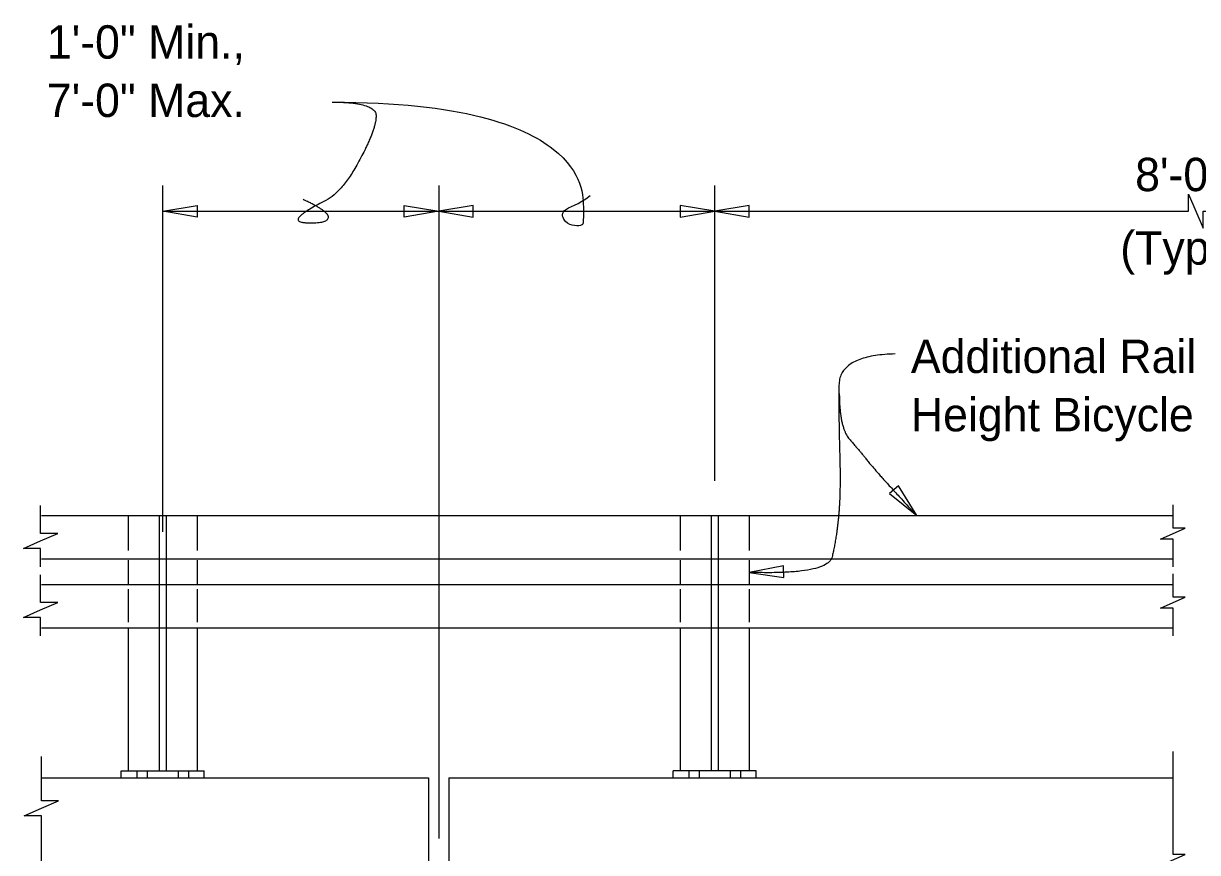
# Model space of a CAD drawing. Extents: x 120680.2 to 120752.3, y 120667.6 to 120707.3.
# Drawn here: x 120682.23 to 120689.32, y 120699.34 to 120704.35 of the extents above; entities that cross this region are included whole.
import ezdxf

# ---------------------------------------------------------------- set-up
doc = ezdxf.new("R2010")
doc.units = 0
for name, color, linetype in [('CL_Minor', 7, 'Continuous'), ('Dimension', 7, 'Continuous'), ('ParapetConc', 7, 'Continuous'), ('PedRail', 7, 'Continuous'), ('TextStructures', 7, 'Continuous')]:
    doc.layers.add(name, color=color, linetype=linetype)

msp = doc.modelspace()

# ---------------------------------------------------------------- linework, layer by layer
at = {"layer": 'CL_Minor'}
msp.add_line((120684.7404, 120703.3696), (120684.7404, 120699.4277), dxfattribs=at)
at = {"layer": 'Dimension'}
for p, q in [((120683.0736, 120701.279), (120683.0736, 120703.3696)), ((120686.4071, 120701.5877), (120686.4071, 120703.3696))]:
    msp.add_line(p, q, dxfattribs=at)
for points in [[(120686.4071, 120703.2151), (120689.2675, 120703.2151), (120689.2675, 120703.3184), (120689.3125, 120703.2151), (120689.3575, 120703.1117), (120689.3575, 120703.2151), (120693.5939, 120703.2151)], [(120683.0736, 120703.2151), (120684.7404, 120703.2151)], [(120684.7404, 120703.2151), (120686.4071, 120703.2151)], [(120682.3361, 120701.0691), (120682.3361, 120701.1797), (120682.2328, 120701.1797), (120682.3361, 120701.2247), (120682.4394, 120701.2697), (120682.3361, 120701.2697), (120682.3361, 120701.4377)], [(120689.1759, 120701.069), (120689.1759, 120701.2356), (120689.0984, 120701.2356), (120689.2484, 120701.3018), (120689.1759, 120701.3018), (120689.1759, 120701.4427)], [(120682.3361, 120700.6524), (120682.3361, 120700.7631), (120682.2328, 120700.7631), (120682.3361, 120700.8081), (120682.4394, 120700.8531), (120682.3361, 120700.8531), (120682.3361, 120701.021)], [(120689.1759, 120700.6523), (120689.1759, 120700.8189), (120689.0984, 120700.8189), (120689.2484, 120700.8852), (120689.1759, 120700.8852), (120689.1759, 120701.026)], [(120689.1748, 120698.3779), (120689.1748, 120699.2651), (120689.0973, 120699.2651), (120689.2473, 120699.3314), (120689.1748, 120699.3314), (120689.1748, 120699.9541)], [(120682.341, 120698.7651), (120682.341, 120699.566), (120682.2376, 120699.566), (120682.341, 120699.611), (120682.4443, 120699.656), (120682.341, 120699.656), (120682.341, 120699.9246)]]:
    msp.add_lwpolyline(points, dxfattribs=at)
for points in [[(120683.0736, 120703.2151), (120683.2819, 120703.2503), (120683.2819, 120703.1798)], [(120684.7404, 120703.2151), (120684.5321, 120703.1798), (120684.5321, 120703.2503)], [(120684.7404, 120703.2151), (120684.9486, 120703.1798), (120684.9486, 120703.2503)], [(120686.4071, 120703.2151), (120686.1988, 120703.2503), (120686.1988, 120703.1798)], [(120686.4071, 120703.2151), (120686.6153, 120703.1798), (120686.6153, 120703.2503)], [(120687.6271, 120701.3779), (120687.5162, 120701.5577), (120687.4632, 120701.5111)], [(120686.6154, 120701.0348), (120686.8243, 120701.0036), (120686.8229, 120701.0742)]]:
    msp.add_lwpolyline(points, close=True, dxfattribs=at)
for points, degree in [([(120684.0979, 120703.8733), (120684.3623, 120703.8733), (120684.3623, 120703.7087), (120684.1567, 120703.3268), (120683.9392, 120703.221), (120683.8629, 120703.1446), (120684.0744, 120703.1446), (120684.0744, 120703.2151), (120683.9216, 120703.2857)], 2), ([(120684.0979, 120703.8733), (120684.8853, 120703.8733), (120685.6139, 120703.5912), (120685.6139, 120703.16), (120685.6139, 120703.1276), (120685.5607, 120703.1248), (120685.5034, 120703.1428), (120685.4637, 120703.2258), (120685.5851, 120703.2549), (120685.6551, 120703.3092)], 3), ([(120687.4974, 120702.3533), (120687.1593, 120702.346), (120687.1552, 120701.9825), (120687.1688, 120701.5209), (120687.1418, 120701.2328), (120687.0887, 120701.0202), (120686.6154, 120701.0348)], 2), ([(120687.1596, 120702.1148), (120687.1606, 120701.9069), (120687.2832, 120701.7687), (120687.3834, 120701.6408), (120687.6271, 120701.3779)], 2)]:
    msp.add_open_spline(points, degree=degree, dxfattribs=at)
at = {"layer": 'ParapetConc'}
for p, q in [((120682.3425, 120699.7946), (120684.6791, 120699.7946)), ((120684.6791, 120699.7946), (120684.6791, 120697.1279)), ((120684.8016, 120699.7946), (120684.8016, 120697.1279)), ((120684.8016, 120699.7946), (120689.1748, 120699.7946))]:
    msp.add_line(p, q, dxfattribs=at)
at = {"layer": 'PedRail'}
for p, q in [((120682.3425, 120701.3779), (120689.1748, 120701.3779)), ((120682.8653, 120701.3779), (120682.8653, 120701.1671)), ((120683.0528, 120701.3779), (120683.0528, 120700.7007)), ((120683.0945, 120701.3779), (120683.0945, 120700.7007)), ((120683.282, 120701.3779), (120683.282, 120701.1671)), ((120686.1987, 120701.3779), (120686.1987, 120701.1671)), ((120686.3862, 120701.3779), (120686.3862, 120700.7007)), ((120686.4279, 120701.3779), (120686.4279, 120700.7007)), ((120686.6154, 120701.3779), (120686.6154, 120701.1671)), ((120682.3425, 120701.1174), (120689.1748, 120701.1174)), ((120682.8653, 120701.1084), (120682.8653, 120700.9613)), ((120683.282, 120701.1084), (120683.282, 120700.9613)), ((120686.1987, 120701.1084), (120686.1987, 120700.9613)), ((120686.6154, 120701.1084), (120686.6154, 120700.9613)), ((120682.3425, 120700.9613), (120689.1748, 120700.9613)), ((120682.8653, 120700.9345), (120682.8653, 120700.7342)), ((120683.282, 120700.9345), (120683.282, 120700.7342)), ((120686.1987, 120700.9345), (120686.1987, 120700.7342)), ((120686.6154, 120700.9345), (120686.6154, 120700.7342)), ((120682.3425, 120700.7007), (120689.1748, 120700.7007)), ((120682.8653, 120700.7007), (120682.8653, 120699.8363)), ((120683.0528, 120700.7007), (120683.0528, 120699.8363)), ((120683.0945, 120700.7007), (120683.0945, 120699.8363)), ((120683.282, 120700.7007), (120683.282, 120699.8363)), ((120686.1987, 120700.7007), (120686.1987, 120699.8363)), ((120686.3862, 120700.7007), (120686.3862, 120699.8363)), ((120686.4279, 120700.7007), (120686.4279, 120699.8363)), ((120686.6154, 120700.7007), (120686.6154, 120699.8363)), ((120682.8236, 120699.7946), (120682.8236, 120699.8363)), ((120682.8236, 120699.8363), (120683.3236, 120699.8363)), ((120682.9174, 120699.8363), (120682.9174, 120699.7946)), ((120682.9799, 120699.8363), (120682.9799, 120699.7946)), ((120683.1674, 120699.8363), (120683.1674, 120699.7946)), ((120683.2299, 120699.8363), (120683.2299, 120699.7946)), ((120683.3236, 120699.7946), (120683.3236, 120699.8363)), ((120686.6571, 120699.8363), (120686.1571, 120699.8363)), ((120686.1571, 120699.7946), (120686.1571, 120699.8363)), ((120686.2508, 120699.8363), (120686.2508, 120699.7946)), ((120686.3133, 120699.8363), (120686.3133, 120699.7946)), ((120686.5008, 120699.8363), (120686.5008, 120699.7946)), ((120686.5633, 120699.8363), (120686.5633, 120699.7946)), ((120686.6571, 120699.7946), (120686.6571, 120699.8363))]:
    msp.add_line(p, q, dxfattribs=at)

# ---------------------------------------------------------------- texts
at = {"layer": 'TextStructures'}
for s, p in [('1\'-0" Min.,', (120682.3739, 120704.1358)), ('7\'-0" Max.', (120682.3739, 120703.7838)), ('8\'-0" Maximum', (120688.9462, 120703.336)), ('(Typ. all Posts)', (120688.8564, 120702.8925)), ('Additional Rail required for Special ', (120687.5918, 120702.2383)), ('Height Bicycle Rail with Post "B"', (120687.5918, 120701.8863))]:
    msp.add_text(s, height=0.2016, dxfattribs=at).set_placement(p)

doc.saveas('drawing.dxf')
